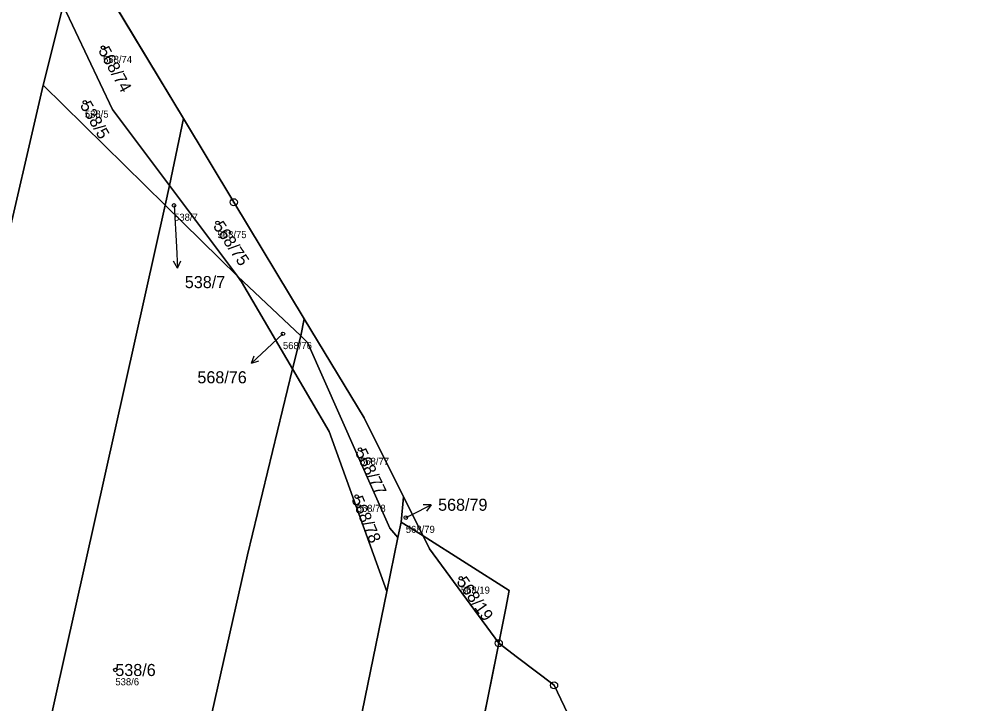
# Model space of a CAD drawing. Extents: x -732749 to -730903, y -1025757 to -1023435.
# Drawn here: x -731643.2 to -731507.8, y -1024635.5 to -1024539 of the extents above; entities that cross this region are included whole.
import ezdxf

# ---------------------------------------------------------------- set-up
doc = ezdxf.new("R2010")
doc.units = 0
for name, color, linetype in [('Definiční body', 7, 'Continuous'), ('Hranice parcel', 7, 'Continuous'), ('Parcelní čísla', 7, 'Continuous'), ('Polygon parcely', 7, 'Continuous'), ('Pop  PČ popisy', 7, 'Continuous'), ('Značky bodu BP', 7, 'Continuous')]:
    doc.layers.add(name, color=color, linetype=linetype)

msp = doc.modelspace()

# ---------------------------------------------------------------- linework, layer by layer
at = {"layer": 'Definiční body'}
for centre in [(-731631.39, -1024542.98), (-731633.96, -1024550.69), (-731621.38, -1024565.23), (-731615.25, -1024567.68), (-731606.03, -1024583.33), (-731595.16, -1024599.65), (-731595.64, -1024606.28), (-731588.71, -1024609.24), (-731580.94, -1024617.81), (-731629.66, -1024630.73)]:
    msp.add_circle(centre, 0.25, dxfattribs=at)
at = {"layer": 'Hranice parcel'}
for p, q in [((-731634.13, -1024529.62), (-731620.06, -1024552.99)), ((-731639.82, -1024548.26), (-731637.02, -1024537.04)), ((-731630.06, -1024551.69), (-731637.02, -1024537.04)), ((-731622.62, -1024565.19), (-731639.82, -1024548.26)), ((-731622.04, -1024562.41), (-731630.06, -1024551.69)), ((-731622.04, -1024562.41), (-731620.06, -1024552.99)), ((-731622.62, -1024565.19), (-731622.04, -1024562.41)), ((-731612.44, -1024575.22), (-731622.04, -1024562.41)), ((-731612.44, -1024575.22), (-731622.62, -1024565.19)), ((-731612.44, -1024575.22), (-731603.53, -1024583.61)), ((-731611.87, -1024575.98), (-731612.44, -1024575.22)), ((-731604.66, -1024588.27), (-731611.87, -1024575.98)), ((-731603.53, -1024583.61), (-731603.04, -1024581.2)), ((-731604.66, -1024588.27), (-731603.53, -1024583.61)), ((-731589.37, -1024609.87), (-731589.01, -1024606.33)), ((-731589.01, -1024606.33), (-731586.26, -1024611.83)), ((-731589.37, -1024609.87), (-731589.82, -1024612.04)), ((-731589.82, -1024612.04), (-731591.37, -1024619.64)), ((-731591.37, -1024619.64), (-731606.01, -1024690.94)), ((-731578.1, -1024639.37), (-731575.6, -1024626.96))]:
    msp.add_line(p, q, dxfattribs=at)
for points in [[(-731639.82, -1024548.26), (-731645.79, -1024574.11), (-731648.95, -1024588.3)], [(-731620.06, -1024552.99), (-731612.96, -1024564.78), (-731603.04, -1024581.2)], [(-731652.88, -1024703.31), (-731639.56, -1024641.06), (-731622.62, -1024565.19)], [(-731603.04, -1024581.2), (-731594.59, -1024595.19), (-731589.01, -1024606.33)], [(-731603.53, -1024583.61), (-731602.55, -1024584.54), (-731590.95, -1024610.74), (-731589.82, -1024612.04)], [(-731629.2, -1024697.06), (-731623.62, -1024670.48), (-731611.05, -1024614.5), (-731604.66, -1024588.27)], [(-731591.37, -1024619.64), (-731599.49, -1024597.09), (-731604.66, -1024588.27)], [(-731586.26, -1024611.83), (-731587.23, -1024611.22), (-731589.37, -1024609.87)], [(-731586.26, -1024611.83), (-731574.11, -1024619.51), (-731574.61, -1024622.02), (-731575.6, -1024626.96)], [(-731575.6, -1024626.96), (-731585.35, -1024613.66), (-731586.26, -1024611.83)], [(-731575.6, -1024626.96), (-731572.94, -1024628.97), (-731567.8, -1024632.89), (-731559.59, -1024650.04)]]:
    msp.add_lwpolyline(points, dxfattribs=at)
at = {"layer": 'Polygon parcely'}
for points in [[(-731637.02, -1024537.04), (-731643.32, -1024523.8), (-731650.19, -1024506.59), (-731656.73, -1024555.17), (-731653.71, -1024557.46), (-731645.4, -1024563.74), (-731648.54, -1024585.48), (-731648.95, -1024588.3), (-731645.79, -1024574.11), (-731639.82, -1024548.26)], [(-731620.06, -1024552.99), (-731634.13, -1024529.62), (-731634.87, -1024528.39), (-731637.02, -1024537.04), (-731630.06, -1024551.69), (-731622.04, -1024562.41)], [(-731630.06, -1024551.69), (-731637.02, -1024537.04), (-731639.82, -1024548.26), (-731622.62, -1024565.19), (-731622.04, -1024562.41)], [(-731652.18, -1024610.53), (-731657.78, -1024635.81), (-731662.99, -1024660.26), (-731668.32, -1024684.91), (-731673.59, -1024708.77), (-731652.88, -1024703.31), (-731639.56, -1024641.06), (-731622.62, -1024565.19), (-731639.82, -1024548.26), (-731645.79, -1024574.11), (-731648.95, -1024588.3)], [(-731603.53, -1024583.61), (-731603.04, -1024581.2), (-731612.96, -1024564.78), (-731620.06, -1024552.99), (-731622.04, -1024562.41), (-731612.44, -1024575.22)], [(-731612.44, -1024575.22), (-731622.04, -1024562.41), (-731622.62, -1024565.19)], [(-731623.62, -1024670.48), (-731611.05, -1024614.5), (-731604.66, -1024588.27), (-731611.87, -1024575.98), (-731612.44, -1024575.22), (-731622.62, -1024565.19), (-731639.56, -1024641.06), (-731652.88, -1024703.31), (-731629.2, -1024697.06)], [(-731603.53, -1024583.61), (-731612.44, -1024575.22), (-731611.87, -1024575.98), (-731604.66, -1024588.27)], [(-731589.01, -1024606.33), (-731594.59, -1024595.19), (-731603.04, -1024581.2), (-731603.53, -1024583.61), (-731602.55, -1024584.54), (-731590.95, -1024610.74), (-731589.82, -1024612.04), (-731589.37, -1024609.87)], [(-731591.37, -1024619.64), (-731589.82, -1024612.04), (-731590.95, -1024610.74), (-731602.55, -1024584.54), (-731603.53, -1024583.61), (-731604.66, -1024588.27), (-731599.49, -1024597.09)], [(-731599.49, -1024597.09), (-731604.66, -1024588.27), (-731611.05, -1024614.5), (-731623.62, -1024670.48), (-731629.2, -1024697.06), (-731606.01, -1024690.94), (-731591.37, -1024619.64)], [(-731589.37, -1024609.87), (-731587.23, -1024611.22), (-731586.26, -1024611.83), (-731589.01, -1024606.33)], [(-731606.01, -1024690.94), (-731604.64, -1024690.58), (-731600.23, -1024689.56), (-731591.69, -1024686.82), (-731587.36, -1024685.42), (-731582.04, -1024659), (-731590.6, -1024657.11), (-731589.78, -1024653.18), (-731592.14, -1024652.67), (-731590.37, -1024644.55), (-731588.01, -1024645.06), (-731586.4, -1024637.6), (-731578.1, -1024639.37), (-731575.6, -1024626.96), (-731585.35, -1024613.66), (-731586.26, -1024611.83), (-731587.23, -1024611.22), (-731589.37, -1024609.87), (-731589.82, -1024612.04), (-731591.37, -1024619.64)], [(-731586.26, -1024611.83), (-731585.35, -1024613.66), (-731575.6, -1024626.96), (-731574.61, -1024622.02), (-731574.11, -1024619.51)], [(-731576.48, -1024639.71), (-731580.77, -1024659.28), (-731582.04, -1024659), (-731587.36, -1024685.42), (-731584.09, -1024684.37), (-731565.14, -1024678.28), (-731562.95, -1024665.44), (-731559.59, -1024650.04), (-731567.8, -1024632.89), (-731572.94, -1024628.97), (-731575.6, -1024626.96), (-731578.1, -1024639.37)]]:
    msp.add_lwpolyline(points, close=True, dxfattribs=at)
msp.add_lwpolyline([(-731634.13, -1024529.62), (-731620.06, -1024552.99), (-731612.96, -1024564.78), (-731603.04, -1024581.2), (-731594.59, -1024595.19), (-731589.01, -1024606.33), (-731586.26, -1024611.83), (-731574.11, -1024619.51), (-731574.61, -1024622.02), (-731575.6, -1024626.96), (-731572.94, -1024628.97), (-731567.8, -1024632.89), (-731559.59, -1024650.04), (-731557.09, -1024655.26), (-731550.05, -1024657.9), (-731546.94, -1024659.07), (-731542.38, -1024659.37), (-731537.37, -1024659.7), (-731528.58, -1024660.28), (-731515.11, -1024654.99), (-731512.19, -1024653.84), (-731492.81, -1024644.46)], dxfattribs=at)
at = {"layer": 'Pop  PČ popisy'}
for p, q in [((-731621.38, -1024565.23), (-731621.04, -1024571.07)), ((-731621.04, -1024571.07), (-731620.88, -1024574.07)), ((-731620.88, -1024574.07), (-731621.44, -1024573.09)), ((-731620.88, -1024574.07), (-731620.44, -1024573.04)), ((-731606.03, -1024583.33), (-731608.29, -1024585.43)), ((-731608.29, -1024585.43), (-731610.48, -1024587.48)), ((-731610.48, -1024587.48), (-731610.09, -1024586.43)), ((-731610.48, -1024587.48), (-731609.41, -1024587.16)), ((-731587.82, -1024608.79), (-731585.15, -1024607.43)), ((-731585.15, -1024607.43), (-731586.27, -1024607.44)), ((-731585.15, -1024607.43), (-731585.81, -1024608.33)), ((-731588.71, -1024609.24), (-731587.82, -1024608.79))]:
    msp.add_line(p, q, dxfattribs=at)
at = {"layer": 'Značky bodu BP'}
for centre, radius in [((-731612.96, -1024564.78), 0.5), ((-731612.96, -1024564.78), 0.0303), ((-731575.6, -1024626.96), 0.5), ((-731575.6, -1024626.96), 0.0303), ((-731567.8, -1024632.89), 0.5), ((-731567.8, -1024632.89), 0.0303)]:
    msp.add_circle(centre, radius, dxfattribs=at)

# ---------------------------------------------------------------- texts
at = {"layer": 'Definiční body'}
for s, p in [('568/74', (-731631.39, -1024545.14)), ('538/5', (-731633.96, -1024552.85)), ('538/7', (-731621.38, -1024567.39)), ('568/75', (-731615.25, -1024569.84)), ('568/76', (-731606.03, -1024585.49)), ('568/77', (-731595.16, -1024601.81)), ('568/78', (-731595.64, -1024608.44)), ('568/79', (-731588.71, -1024611.4)), ('568/19', (-731580.94, -1024619.97)), ('538/6', (-731629.66, -1024632.89))]:
    msp.add_text(s, height=1, dxfattribs=at).set_placement(p)
at = {"layer": 'Parcelní čísla'}
for s, rotation, p in [('568/74', 299, (-731632.13, -1024543.39)), ('538/5', 300, (-731634.7, -1024551.11)), ('568/75', 304, (-731615.95, -1024568.16)), ('568/77', 296, (-731595.92, -1024600.02)), ('568/78', 293, (-731596.42, -1024606.61)), ('568/19', 305, (-731581.64, -1024618.3))]:
    msp.add_text(s, height=1.7, rotation=rotation, dxfattribs=at).set_placement(p)
for s, p in [('538/7', (-731619.86, -1024576.89)), ('568/76', (-731618.09, -1024590.31)), ('568/79', (-731584.15, -1024608.28)), ('538/6', (-731629.66, -1024631.58))]:
    msp.add_text(s, height=1.7, dxfattribs=at).set_placement(p)

doc.saveas('drawing.dxf')
